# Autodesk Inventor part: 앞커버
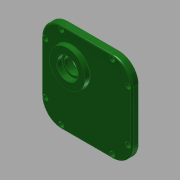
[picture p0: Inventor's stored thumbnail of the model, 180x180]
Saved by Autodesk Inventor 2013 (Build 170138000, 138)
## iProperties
Created: 2016-12
Part Number: 앞커버
Material: 일반
Document SubType Name: Modeling
Designer: mduedu
Density: 1 g/cm^3
Mass: 191.493 g
Surface Area: 476.271 cm^2
Volume: 191.493 cm^3
Author: mduedu
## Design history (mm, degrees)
sketch "스케치1"
  geometry: L1 (-46, 42)-(-46, -36); L2 (-16, 72)-(62, 72); L3 (92, 42)-(92, -36); L4 (62, -66)-(-16, -66); A1 r 30 centre (-16, -36) between (-46, -36) and (-16, -66); A2 r 30 centre (62, 42) between (92, 42) and (62, 72); A3 r 30 centre (62, -36) between (62, -66) and (92, -36); A4 r 30 centre (-16, 42) between (-16, 72) and (-46, 42); 1 further point
  constraints: 8 end point, 8 point on circle, 8 tangent, 4 centre point, 3 equal radius, 2 perpendicular, 1 horizontal
  dimensions: "d89" = 30 radius of A2; "d90" = 92 distance from line of L3 point (0, 0); "d91" = 138 distance between parallel lines of L4 L2; "d92" = 72 distance from line of point (0, 0) L2; "d114" = 46 distance from line of point (0, 0) L1
extrude "돌출1" new body sketch "스케치1" distance "d3" = 10; taper "d4" = 0 deg
sketch "스케치2"
  geometry: C1 r 21 at (0, 26); 1 further point
  constraints: 1 centre point, 1 vertical alignment
  dimensions: "d5" = 42 diameter of C1; "d7" = 26 distance of C1.centre point (0, 0)
extrude "돌출2" join sketch "스케치2" distance "d8" = 7; taper "d9" = 0 deg
sketch "스케치3"
  geometry: C1 r 15 at (0, -28.87); C2 r 21 at (0, 26) reference; C3 r 15 at (-54.87, 26); 1 further point
  constraints: 2 centre point, 1 horizontal alignment, 1 vertical alignment
  dimensions: "d10" = 30 diameter of C1; "d71" = 54.87 distance of C1.centre C2.centre; "d94" = 30 diameter of C3; "d95" = 54.87 distance of C2.centre C3.centre
extrude "돌출3" join sketch "스케치3" distance "d12" = 7; taper "d13" = 0 deg; dims "d50" = 90 deg
sketch "스케치4"
  geometry: C1 r 21 at (0, 26) reference; C2 r 28 at (0, 26); 1 further point
  constraints: 1 centre point, 1 coincident
  dimensions: "d14" = 56 diameter of C2
extrude "돌출4" join sketch "스케치4" distance "d15" = 7; taper "d16" = -5 deg
hole "구멍1" diameter "d19" = 35; stored, may be unused: countersink angle "d23" = 90 deg, drill point angle "d25" = 0 deg; dims "d17" = 10, "d18" = 10, "d20" = 6, "d21" = 4, "d22" = 2, "d24" = 10
hole "구멍2" diameter "d28" = 22; stored, may be unused: countersink angle "d32" = 90 deg, drill point angle "d34" = 0 deg; dims "d26" = 10, "d27" = 10, "d29" = 6, "d30" = 4, "d31" = 2, "d33" = 7
hole "구멍8" diameter "d98" = 22; stored, may be unused: countersink angle "d102" = 90 deg, drill point angle "d104" = 0 deg; dims "d96" = 10, "d97" = 10, "d99" = 6, "d100" = 4, "d101" = 2, "d103" = 7
hole "구멍3" diameter "d37" = 19; stored, may be unused: countersink angle "d41" = 90 deg, drill point angle "d43" = 0 deg; dims "d35" = 10, "d36" = 10, "d38" = 6, "d39" = 4, "d40" = 2, "d42" = 1
hole "구멍9" diameter "d107" = 19; stored, may be unused: countersink angle "d111" = 90 deg, drill point angle "d113" = 0 deg; dims "d105" = 10, "d106" = 10, "d108" = 6, "d109" = 4, "d110" = 2, "d112" = 1
hole "구멍4" diameter "d46" = 32; stored, may be unused: countersink angle "d50" = 90 deg, drill point angle "d52" = 0 deg; dims "d44" = 10, "d45" = 10, "d47" = 6, "d48" = 4, "d49" = 2, "d51" = 8
hole "구멍5" diameter "d55" = 25; stored, may be unused: countersink angle "d59" = 90 deg, drill point angle "d61" = 0 deg; dims "d53" = 10, "d54" = 10, "d56" = 6, "d57" = 4, "d58" = 2, "d60" = 8
fillet "모깎기1" dims "d62" = 0.3
fillet "모깎기2" dims "d63" = 2
chamfer "모따기1" distance "d64" = 1; stored, may be unused: second distance "d65" = 2, angle "d66" = 45 deg
fillet "모깎기4" dims "d68" = 2
fillet "모깎기5" dims "d69" = 0.3
fillet "모깎기6" dims "d70" = 2
sketch "스케치5"
  geometry: L1 (62, 72)-(-16, 72) reference; L2 (92, -36)-(92, 42) reference; L3 (-16, -66)-(62, -66) reference; L4 (-46, 42)-(-46, -36) reference; L5 (-40, 42)-(-40, -36); L6 (-16, -60)-(62, -60); L7 (86, -36)-(86, 42); L8 (62, 66)-(-16, 66); A1 r 30 centre (62, 42) between (92, 42) and (62, 72) reference; A2 r 30 centre (62, -36) between (62, -66) and (92, -36) reference; A3 r 30 centre (-16, -36) between (-46, -36) and (-16, -66) reference; A4 r 30 centre (-16, 42) between (-16, 72) and (-46, 42) reference; A5 r 24 centre (-16, -36) between (-40, -36) and (-16, -60); A6 r 24 centre (62, -36) between (62, -60) and (86, -36); A7 r 24 centre (62, 42) between (86, 42) and (62, 66); A8 r 24 centre (-16, 42) between (-16, 66) and (-40, 42)
  constraints: 8 end point, 8 point on circle, 4 centre point, 7 other
  dimensions: "d93" = 6 distance between parallel lines of L5 L4
sketch "스케치7"
  geometry: L1 (62, 66)-(-16, 66) reference; L2 (86, -36)-(86, 42) reference; L3 (-16, -60)-(62, -60) reference; L4 (-40, 42)-(-40, -36) reference; A1 r 24 centre (62, 42) between (86, 42) and (62, 66) reference; A2 r 24 centre (62, -36) between (62, -60) and (86, -36) reference; A3 r 24 centre (-16, -36) between (-40, -36) and (-16, -60) reference; A4 r 24 centre (-16, 42) between (-16, 66) and (-40, 42) reference; 8 further points
  constraints: 8 coincident
hole "구멍7" sketch "스케치7" at (-40, 42), (-40, -36), (-16, -60), (62, -60), (86, -36), (86, 42), (62, 66), (-16, 66) diameter "d80" = 4.5; stored, may be unused: countersink angle "d84" = 90 deg, drill point angle "d86" = 0 deg; dims "d81" = 6, "d82" = 8, "d83" = 4.6, "d85" = 8
node "솔리드1"
